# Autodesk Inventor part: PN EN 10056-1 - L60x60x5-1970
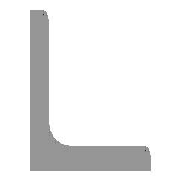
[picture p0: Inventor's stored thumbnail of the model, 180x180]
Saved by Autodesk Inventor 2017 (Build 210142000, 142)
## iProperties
Created: 2016-02
Part Number: PN EN 10056-1 - L60x60x5-1970
Material: Stal, miękka
Description: Kątownik równoramienny
Document SubType Name: Modeling
Standard: PN
Designer: X
Standards Organization: PN
Language: pl-PL
Size Designation: L60x60x5
Categories: <MemberInstance><Categories><Category DisplayName="Kształtowniki konstrukcyjne" InternalName="089c4875-fa83-4c05-b084-43b9cc11f5ed" Mnemonic="GRDR"><CategoryPar
Stock Number: L60x60x5
Density: 7.85 g/cm^3
Appearance: Częściowo polerowana
Mass: 8998.29 g
Surface Area: 4604.35 cm^2
Volume: 1146.28 cm^3
_CCFamilyMember: 130
_CCFamilyDisplayName: PN EN 10056-1 (Kątownik równoramienny) - Kątownik równoramienny
_FrameMemberDoc: Frame Member File
_Version: 15.0.0
_GetPNFromCC: 1
IsCustomPart: 1
G_W: 60,000 mm
G_H: 60,000 mm
G_L: 1970,000 mm
Author: X
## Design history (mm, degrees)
node "Płaszczyzna początkowa"
node "Płaszczyzna końcowa"
sketch "Szkic"
  geometry: L1 (-11.517, -3.517)-(-11.517, 39.483); L2 (-16.517, 43.483)-(-15.517, 43.483); L3 (-16.517, -16.517)-(-16.517, 43.483); L4 (-16.517, -16.517)-(43.483, -16.517); L5 (43.483, -15.517)-(43.483, -16.517); L6 (-3.517, -11.517)-(39.483, -11.517); L7 (0, 56.477)-(0, -28.683) reference; L8 (-28.683, 0)-(56.477, 0) reference; A1 r 8 centre (-3.517, -3.517) between (-11.517, -3.517) and (-3.517, -11.517); A2 r 4 centre (-15.517, 39.483) between (-11.517, 39.483) and (-15.517, 43.483); A3 r 4 centre (39.483, -15.517) between (43.483, -15.517) and (39.483, -11.517); 3 further points
  constraints: 12 end point, 6 point on circle, 6 point on line, 6 tangent, 3 centre point, 3 horizontal, 3 vertical, 1 equal radius
  dimensions: "d4" = 60 distance of L3.start L4.end (= b); "d6" = 60 distance of L3.start L2.start (= b); "d8" = 5 distance of point (43.483, -11.517) L4.end (= ParT); "d10" = 5 distance of L2.start point (-11.517, 43.483) (= ParT); "d17" = 8 radius of A1 (= R); "d18" = 4 radius of A2 (= R1); "d19" = 16.51748 distance between parallel lines of L8 L4 (= ex); "d20" = 16.51748 distance between parallel lines of L3 L7 (= d19)
extrude "Bryła" new body sketch "Szkic" stored distance "d11" = 1970 (= G_L); taper "d12" = 0 deg
node "Driven Length"
  sketch "Sketch3"
    geometry: L1 (0, 0)-(10, 0) reference
    constraints: 2 end point, 1 horizontal
  workplane "Work Plane10"
  sketch "Sketch4"
    geometry: L1 (-2, 0)-(12, 0) reference; L2 (-2, 1970)-(12, 1970) reference
    dimensions: "d24" = 1970 distance between parallel lines of L1 L2 (derived)
body "Solid1"
other parameters: "b" = 60 [user parameter; used in 3 equation terms], "ParT" = 5 [user parameter; used in 3 equation terms], "R" = 8 [user parameter; used in 1 equation term], "R1" = 4 [user parameter; used in 1 equation term], "G_L" = 1970 (= d24) [user parameter; used in 1 equation term], "d7" = 4 (derived), "d9" = 4 (derived), "ex" = 16.51748 (computed from b, ParT) [user parameter; used in 1 equation term], "G_OFFSET_START" = 0 [user parameter; used in 1 equation term], "G_OFFSET_END" = 0 [user parameter; used in 1 equation term], "d21" = 0 (computed from G_OFFSET_START), "d23" = 90 deg
